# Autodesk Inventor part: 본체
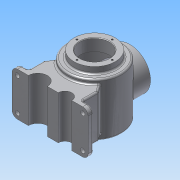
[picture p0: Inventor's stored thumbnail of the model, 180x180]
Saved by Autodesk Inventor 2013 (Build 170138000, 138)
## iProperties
Created: 2018-08
Part Number: 본체
Material: 알루미늄 6061
Document SubType Name: Modeling
Designer: Administrator
Density: 2.71 g/cm^3
Mass: 1885.08 g
Surface Area: 1089.76 cm^2
Volume: 695.603 cm^3
Author: Administrator
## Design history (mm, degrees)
sketch "스케치4"
  geometry: L1 (0, 160.215)-(0, -160.215); L2 (50, -102.762)-(50, -11); L3 (47, -8)-(41, -8); L4 (38, -5)-(38, 4); L5 (38, 4)-(0, 4); A1 r 116 centre (0, 0) between (0, -116) and (48.248, -105.49); A2 r 3 centre (47, -11) between (50, -11) and (47, -8); A3 r 3 centre (47, -102.762) between (48.248, -105.49) and (50, -102.762); A4 r 3 centre (41, -5) between (38, -5) and (41, -8); 5 further points
  constraints: 10 end point, 9 point on circle, 7 point on line, 6 tangent, 4 centre point, 2 coincident, 2 equal radius, 2 parallel, 2 perpendicular, 1 midpoint, 1 vertical
  dimensions: "d31" = 100 diameter of L2 L1; "d32" = 76 diameter of L4 L1; "d33" = 116 radius of A1; "d34" = 108 distance from line of A1.start L3; "d35" = 12 distance of point (38, -8) L4.end; "d39" = 3 radius of A2
revolve "회전3" sketch "스케치4" stored, may be unused: angle "d38" = 90 deg
sketch "스케치5"
  geometry: L1 (50, -11)-(50, -102.762) reference; L2 (-47, -8)-(47, -8) reference; L3 (40, -21)-(40, -96.125); L4 (37, -18)-(27, -18); L5 (0, 252.733)-(0, -252.733); L6 (27, -18)-(27, 4); L7 (-38, 4)-(38, 4) reference; L8 (27, 4)-(0, 4); A1 r 116 centre (0, 0) between (-48.248, -105.49) and (48.248, -105.49) reference; A2 r 3 centre (47, -102.762) between (48.248, -105.49) and (50, -102.762) reference; A3 r 3 centre (47, -11) between (50, -11) and (47, -8) reference; A4 r 106 centre (0, 0) between (0, -106) and (38.078, -98.925); A5 r 3 centre (37, -21) between (40, -21) and (37, -18); A6 r 3 centre (37, -96.125) between (38.078, -98.925) and (40, -96.125); 4 further points
  constraints: 10 end point, 7 point on circle, 5 point on line, 4 tangent, 3 centre point, 2 collinear, 2 parallel, 2 perpendicular, 1 coincident, 1 equal radius, 1 midpoint
  dimensions: "d41" = 10 distance between parallel lines of L1 L3; "d42" = 10 radial gap between concentric circles of A1 A4; "d43" = 10 distance between parallel lines of L2 L4; "d44" = 54 diameter of L6 L5; "d46" = 3 radius of A5
revolve "회전4" sketch "스케치5" stored, may be unused: angle "d45" = 90 deg
node "작업 평면1"
sketch "스케치6"
  geometry: L1 (-60, -16)-(60, -16); L2 (70, -26)-(70, -86); L3 (60, -96)-(-60, -96); L4 (-70, -86)-(-70, -26); L5 (-70, -16)-(70, -96); L6 (70, -16)-(-70, -96); L7 (-47, -8)-(47, -8) reference; C1 r 4 at (60, -26); C2 r 4 at (60, -86); C3 r 4 at (-60, -26); C4 r 4 at (-60, -86); A1 r 10 centre (60, -26) between (70, -26) and (60, -16); A2 r 10 centre (60, -86) between (60, -96) and (70, -86); A3 r 10 centre (-60, -86) between (-70, -86) and (-60, -96); A4 r 10 centre (-60, -26) between (-60, -16) and (-70, -26); 3 further points
  constraints: 12 end point, 8 centre point, 8 point on circle, 8 point on line, 8 tangent, 4 coincident, 3 midpoint, 2 equal radius, 2 parallel, 1 horizontal, 1 perpendicular, 1 vertical alignment
  dimensions: "d48" = 140 distance of L5.end L6.end; "d49" = 80 distance of L6.start L5.end; "d50" = 10 radius of A1; "d51" = 10 radius of A4; "d52" = 8 distance between parallel lines of L1 L7; "d53" = 8 diameter of C1; "d54" = 8 diameter of C2; "d55" = 8 diameter of C3; "d56" = 8 diameter of C4
extrude "돌출1" join sketch "스케치6" distance "d57" = 10; taper "d58" = 0 deg
sketch "스케치7"
  geometry: L1 (0, 10)-(120, 10) reference; L2 (-10, 0)-(-10, 10) reference; L3 (130, 0)-(130, 10) reference; L4 (130, 10)-(120, 10) reference; L5 (0, 10)-(-10, 10) reference; L6 (-10, 10)-(19.696, 52.41); L7 (130, 10)-(100.304, 52.41); L8 (-10, 10)-(130, 10); C1 r 50 at (60, 82) reference; A1 r 50 centre (60, 82) between (19.696, 52.41) and (100.304, 52.41); 1 further point
  constraints: 6 end point, 2 collinear, 2 point on circle, 2 point on line, 1 centre point, 1 coincident, 1 concentric
  dimensions: "d65" = 35 deg angle of L6 L2; "d66" = 35 deg angle of L7 L3
extrude "돌출2" join sketch "스케치7" distance "d67" = 80; taper "d68" = 0 deg
sketch "스케치8"
  geometry: L1 (130, 10)-(100.304, 52.41) reference; L2 (19.696, 52.41)-(-10, 10) reference; L3 (-10, 0)-(-10, 10) reference; L4 (130, 0)-(130, 10) reference; L5 (-10, 10)-(10, 10); L6 (10, 10)-(10, 38.563); L7 (10, 38.563)-(-10, 38.563); L8 (-10, 38.563)-(-10, 10); L9 (130, 10)-(110, 10); L10 (110, 10)-(110, 38.563); L11 (110, 38.563)-(130, 38.563); L12 (130, 38.563)-(130, 10)
  constraints: 16 end point, 4 parallel, 2 horizontal, 2 perpendicular, 2 point on line
  dimensions: "d69" = 20 distance of L2.end L5.end; "d70" = 20 distance of L1.start L9.end
extrude "돌출3" cut sketch "스케치8" stored distance "d71" = 80; taper "d72" = 0 deg
sketch "스케치9"
  geometry: L1 (120, 0)-(0, 0) reference; L2 (-10, 0)-(-10, 10) reference; L3 (130, 0)-(130, 10) reference; L4 (60, 82)-(60, -47.486); C1 r 17.5 at (82.5, 0); C2 r 12.5 at (32.5, 0); A1 r 50 centre (60, 82) between (19.696, 52.41) and (100.304, 52.41) reference
  constraints: 2 centre point, 2 end point, 2 point on line, 1 coincident, 1 parallel
  dimensions: "d73" = 22.5 distance from line of L4 C1.centre; "d75" = 27.5 distance from line of C2.centre L4; "d76" = 35 diameter of C1; "d77" = 25 diameter of C2
extrude "돌출4" cut sketch "스케치9" stored distance "d78" = 80; taper "d79" = 0 deg
fillet "모깎기1" dims "d80" = 3
fillet "모깎기2" dims "d81" = 3
node "작업 평면3"
sketch "스케치10"
  geometry: L1 (70, -86)-(70, -26) reference; L2 (-47, -8)-(47, -8) reference; C1 r 38 at (0, -58); 1 further point
  constraints: 1 centre point, 1 vertical alignment
  dimensions: "d84" = 76 diameter of C1; "d128" = 50 distance from line of C1.centre L2
extrude "돌출5" join sketch "스케치10" stored distance "d85" = 80; taper "d86" = 0 deg
hole "구멍1" diameter "d89" = 54; stored, may be unused: countersink angle "d93" = 90 deg, drill point angle "d95" = 0 deg; dims "d87" = 10, "d88" = 10, "d90" = 6, "d91" = 4, "d92" = 2, "d94" = 8
fillet "모깎기3" dims "d96" = 3
sketch "스케치11"
  geometry: C1 r 27 at (0, 0) reference; 2 further points
  constraints: 1 horizontal alignment
  dimensions: "d97" = 32.5 distance of C1.centre point (-32.5, 0)
hole "구멍2" sketch "스케치11" at (-32.5, 0) diameter "d98" = 3.242; stored, may be unused: countersink angle "d102" = 90 deg, drill point angle "d104" = 118 deg; dims "d99" = 8, "d100" = 4, "d101" = 2, "d103" = 10
sketch "스케치12"
  geometry: C1 r 27 at (0, 0) reference; 1 further point
  constraints: 1 vertical alignment
  dimensions: "d108" = 32.5 distance of C1.centre point (0, 32.5)
hole "구멍3" sketch "스케치12" at (0, 32.5) diameter "d109" = 3.242; stored, may be unused: countersink angle "d113" = 90 deg, drill point angle "d115" = 118 deg; dims "d110" = 8, "d111" = 4, "d112" = 2, "d114" = 10
chamfer "모따기1" distance "d119" = 1; stored, may be unused: second distance "d120" = 2, angle "d121" = 45 deg
node "작업 평면4"
sketch "스케치13"
  geometry: C1 r 32.5 at (0, 0); 1 further point
  constraints: 1 centre point, 1 coincident, 1 other
  dimensions: "d122" = 65 diameter of C1
feature "엠보싱2" sketch "스케치13" dims "d31" = 100, "d32" = 76, "d33" = 116, "d34" = 108, "d35" = 12, "d39" = 3, "d125" = 0.5, "d126" = 0
fillet "모깎기4" dims "d127" = 3
node "솔리드2"
pattern_circular "원형 패턴1" dims angle "d106" = 360 deg
pattern_circular "원형 패턴2" dims angle "d117" = 360 deg
other parameters: "d0" = 232, "d23" = 10, "d30" = 232, "d47" = -82, "d83" = 65
